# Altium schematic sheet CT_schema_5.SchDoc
size 298 x 177 mm
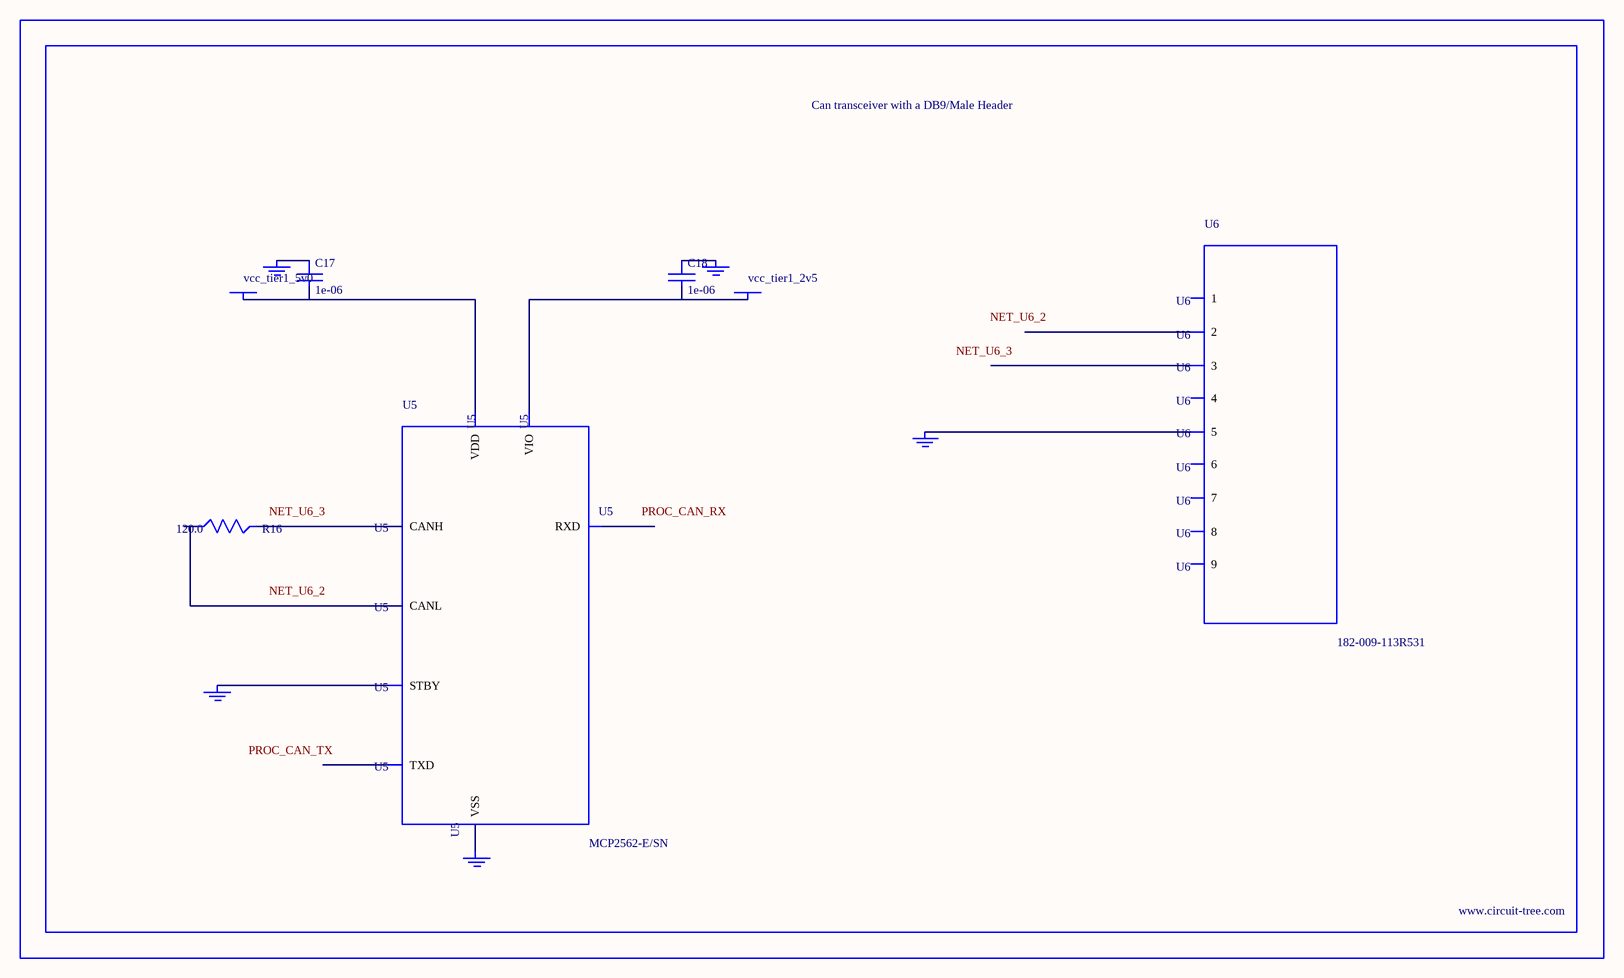
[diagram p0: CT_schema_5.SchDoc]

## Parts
BORDER4  (no value)
C17  1e-06  [C0603]
C18  1e-06  [C0603]
GND_INSTANCE_4_0  (no value)
GND_INSTANCE_4_1  (no value)
GND_INSTANCE_4_2  (no value)
GND_INSTANCE_4_3  (no value)
GND_INSTANCE_4_4  (no value)
POWER_INSTANCE_4_0  vcc_tier1_5v0
POWER_INSTANCE_4_1  vcc_tier1_2v5
R16  120.0  [R0603]
U5  MCP2562-E/SN  [SOIC-8]
U6  182-009-113R531  [182-009-MALE]

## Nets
NetC17_1: C17.1 GND_INSTANCE_4_0.0(GND)
NetC17_2: C17.2 POWER_INSTANCE_4_0.0(PWR) U5.3(VDD)
NetC18_1: C18.1 GND_INSTANCE_4_1.0(GND)
NetC18_2: C18.2 POWER_INSTANCE_4_1.0(PWR) U5.5(VIO)
NetGND_INSTANCE_4_2_0: GND_INSTANCE_4_2.0(GND) U5.8(STBY)
NetGND_INSTANCE_4_3_0: GND_INSTANCE_4_3.0(GND) U5.2(VSS)
NetGND_INSTANCE_4_4_0: GND_INSTANCE_4_4.0(GND) U6.5
NetR16_1: R16.1 U5.6(CANL)
NetR16_2: R16.2 U5.7(CANH)

Not connected (* = marked no-connect by the designer): U5 1(TXD) 4(RXD); U6 1 2 3 4 6 7 8 9

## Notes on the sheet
- Labels drawn without touching a wire or pin: NET_U6_2, NET_U6_3, PROC_CAN_RX, PROC_CAN_TX

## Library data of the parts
BORDER4 = BORDER_PAGE4
C17 C18 = C0603C105K3RACTU
GND_INSTANCE_4_0-GND_INSTANCE_4_4 = GND
POWER_INSTANCE_4_0 POWER_INSTANCE_4_1 = PWR
R16 = RC0603JR-07120RL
